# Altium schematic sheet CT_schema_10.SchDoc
size 274 x 160 mm
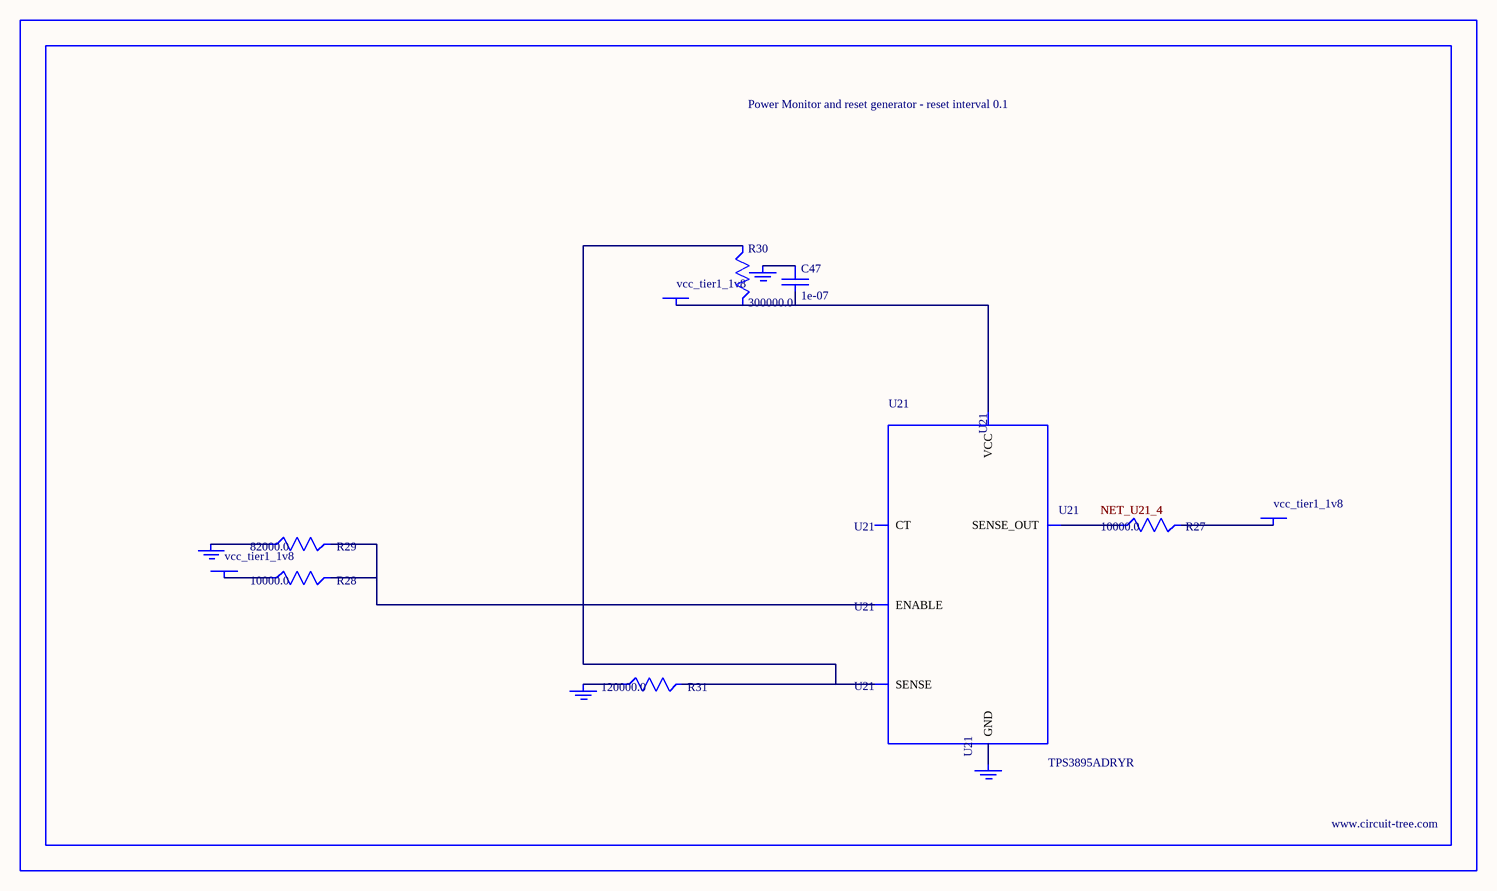
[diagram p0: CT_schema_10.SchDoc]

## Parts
BORDER9  (no value)
C47  1e-07  [C0402]
GND_INSTANCE_9_0  (no value)
GND_INSTANCE_9_1  (no value)
GND_INSTANCE_9_2  (no value)
GND_INSTANCE_9_3  (no value)
POWER_INSTANCE_9_0  vcc_tier1_1v8
POWER_INSTANCE_9_1  vcc_tier1_1v8
POWER_INSTANCE_9_2  vcc_tier1_1v8
R27  10000.0  [R0603]
R28  10000.0  [R0603]
R29  82000.0  [R0603]
R30  300000.0  [R0603]
R31  120000.0  [R0603]
U21  TPS3895ADRYR  [SON-6]

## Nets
NetC47_1: C47.1 GND_INSTANCE_9_2.0(GND)
NetC47_2: C47.2 POWER_INSTANCE_9_2.0(PWR) R30.2 U21.6(VCC)
NetGND_INSTANCE_9_0_0: GND_INSTANCE_9_0.0(GND) R29.1
NetGND_INSTANCE_9_1_0: GND_INSTANCE_9_1.0(GND) R31.1
NetGND_INSTANCE_9_3_0: GND_INSTANCE_9_3.0(GND) U21.2(GND)
NetPOWER_INSTANCE_9_0_0: POWER_INSTANCE_9_0.0(PWR) R28.1
NetPOWER_INSTANCE_9_1_0: POWER_INSTANCE_9_1.0(PWR) R27.2
NetR27_1: R27.1 U21.4(SENSE_OUT)
NetR28_2: R28.2 R29.2 U21.1(ENABLE)
NetR30_1: R30.1 R31.2 U21.3(SENSE)

Not connected (* = marked no-connect by the designer): U21 5(CT)

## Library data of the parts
BORDER9 = BORDER_PAGE9
C47 = C0402C104K3RACTU
GND_INSTANCE_9_0-GND_INSTANCE_9_3 = GND
POWER_INSTANCE_9_0-POWER_INSTANCE_9_2 = PWR
R27 R28 = RC0603JR-0710KL
R29 = RC0603JR-0782KL
R30 = RC0603JR-07300KL
R31 = RC0603JR-07120KL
